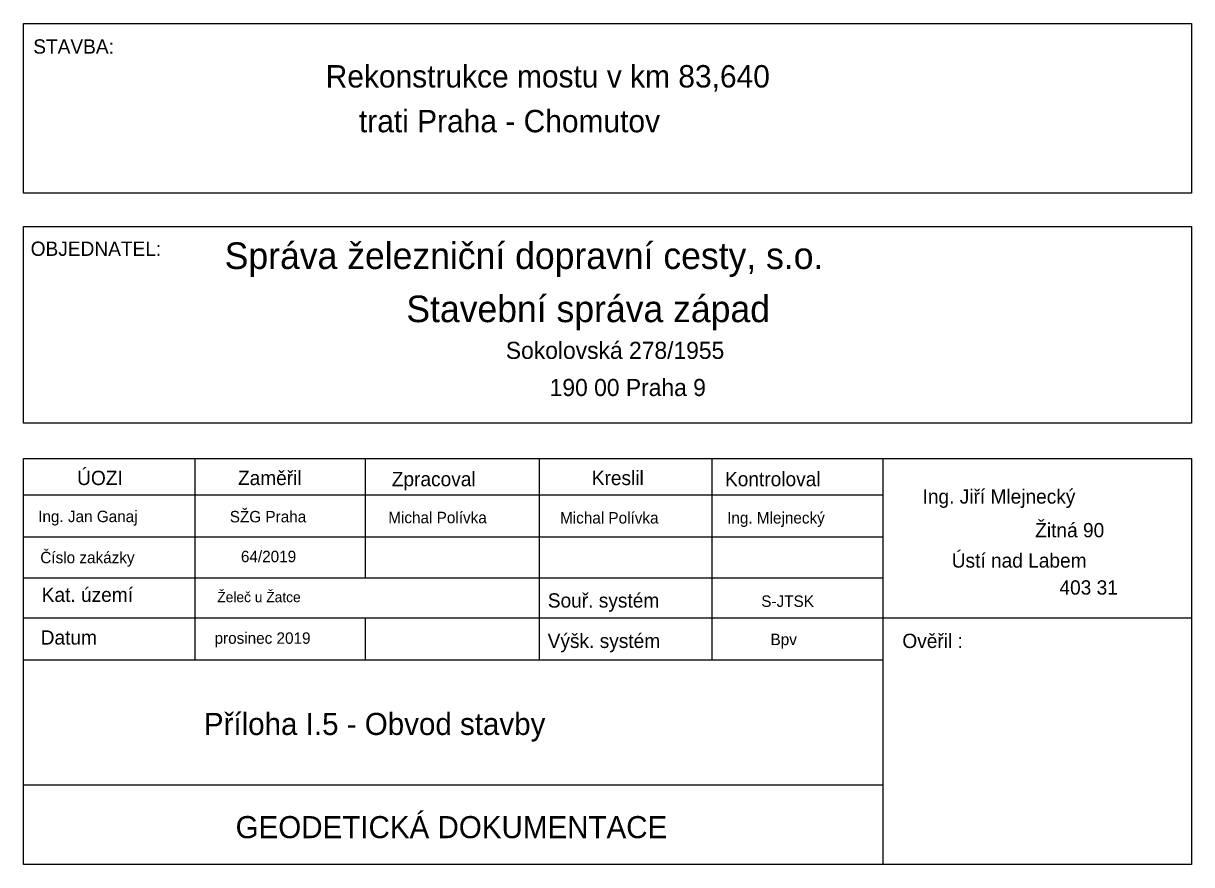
# Model space of a CAD drawing. Extents: x -879530 to -879371, y -1019242 to -1019127.
import ezdxf

# ---------------------------------------------------------------- set-up
doc = ezdxf.new("R2010")
doc.units = 0
doc.layers.add('LEGENDA', color=7, linetype='Continuous')
doc.layers.add('tabulka', color=7, linetype='Continuous')

msp = doc.modelspace()

# ---------------------------------------------------------------- linework, layer by layer
at = {"layer": 'tabulka'}
for p, q in [((-879530.09, -1019186.45), (-879371.44, -1019186.45)), ((-879506.8, -1019186.45), (-879506.8, -1019213.77)), ((-879483.66, -1019186.45), (-879483.66, -1019202.65)), ((-879460.06, -1019186.45), (-879460.06, -1019213.77)), ((-879436.61, -1019186.45), (-879436.61, -1019213.77)), ((-879413.31, -1019241.58), (-879413.31, -1019186.45)), ((-879530.09, -1019191.36), (-879413.31, -1019191.36)), ((-879530.09, -1019197.07), (-879413.31, -1019197.07)), ((-879530.09, -1019202.65), (-879413.31, -1019202.65)), ((-879530.09, -1019208.07), (-879371.44, -1019208.07)), ((-879483.66, -1019208.07), (-879483.66, -1019213.77)), ((-879530.09, -1019213.77), (-879413.31, -1019213.77)), ((-879530.09, -1019230.76), (-879413.31, -1019230.76))]:
    msp.add_line(p, q, dxfattribs=at)
for points in [[(-879530.09, -1019127.36), (-879371.44, -1019127.36), (-879371.44, -1019150.43), (-879530.09, -1019150.43)], [(-879530.09, -1019154.95), (-879371.44, -1019154.95), (-879371.44, -1019181.64), (-879530.09, -1019181.64)]]:
    msp.add_lwpolyline(points, close=True, dxfattribs=at)
msp.add_lwpolyline([(-879371.44, -1019186.45), (-879371.44, -1019241.58), (-879530.09, -1019241.58), (-879530.09, -1019186.45)], dxfattribs=at)

# ---------------------------------------------------------------- texts
at = {"layer": 'LEGENDA'}
for s, p in [('Rekonstrukce mostu v km 83,640 ', (-879489.04, -1019136.07)), ('    trati Praha - Chomutov', (-879489.04, -1019142.15))]:
    msp.add_text(s, height=3.04, dxfattribs=at).set_placement(p)
at = {"layer": 'tabulka'}
for s, height, p in [('STAVBA:', 1.94, (-879528.75, -1019131.47)), ('OBJEDNATEL:', 1.94, (-879529.1, -1019158.93)), ('Správa železniční dopravní cesty, s.o.', 3.61, (-879502.75, -1019160.71)), ('Stavební správa západ', 3.61, (-879478.08, -1019167.93)), ('Sokolovská 278/1955', 2.32, (-879464.57, -1019172.92)), ('190 00 Praha 9', 2.32, (-879458.62, -1019177.96)), ('ÚOZI', 1.94, (-879522.79, -1019190.05)), ('Zaměřil', 1.94, (-879500.95, -1019190.05)), ('Zpracoval', 1.94, (-879480.06, -1019190.2)), ('Kreslil', 1.94, (-879452.9, -1019190.05)), ('Kontroloval', 1.94, (-879434.81, -1019190.2)), ('Ing. Jiří Mlejnecký', 1.94, (-879407.98, -1019192.57)), ('Ing. Jan Ganaj', 1.552, (-879528.08, -1019195.08)), ('SŽG Praha', 1.552, (-879502.06, -1019195.11)), ('Michal Polívka', 1.552, (-879480.54, -1019195.23)), ('Michal Polívka', 1.552, (-879457.21, -1019195.27)), ('Ing. Mlejnecký', 1.552, (-879434.52, -1019195.27)), ('Žitná 90', 1.94, (-879392.68, -1019197.14)), ('Číslo zakázky', 1.552, (-879527.79, -1019200.66)), ('64/2019', 1.552, (-879500.55, -1019200.52)), ('Ústí nad Labem', 1.94, (-879404.02, -1019201.26)), ('403 31', 1.94, (-879389.39, -1019204.92)), ('Kat. území', 1.94, (-879527.6, -1019205.91)), ('Želeč u Žatce', 1.3968, (-879503.75, -1019205.95)), ('Souř. systém', 1.94, (-879458.87, -1019206.68)), ('S-JTSK', 1.552, (-879429.88, -1019206.59)), ('Datum', 1.94, (-879527.74, -1019211.71)), ('prosinec 2019', 1.552, (-879504.13, -1019211.6)), ('Výšk. systém', 1.94, (-879458.89, -1019212.17)), ('Bpv', 1.552, (-879428.62, -1019211.78)), ('Ověřil :', 1.94, (-879410.72, -1019212.17)), ('Příloha I.5 - Obvod stavby', 3, (-879505.58, -1019223.98)), ('GEODETICKÁ DOKUMENTACE ', 3, (-879501.27, -1019237.99))]:
    msp.add_text(s, height=height, dxfattribs=at).set_placement(p)

doc.saveas('drawing.dxf')
